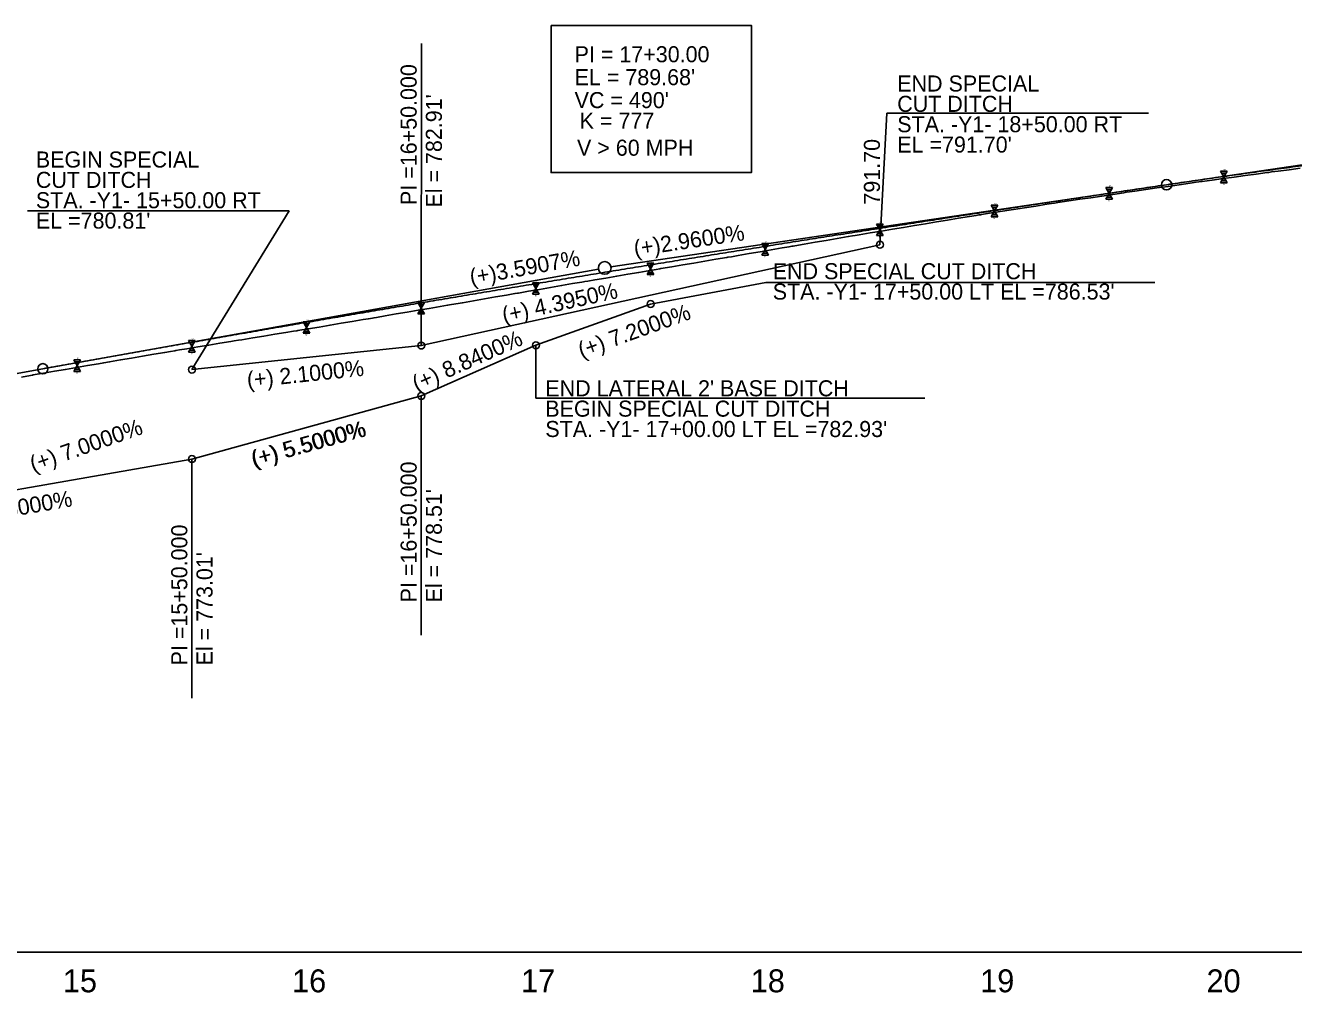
# Model space of a CAD drawing. Extents: x 579185 to 595036, y -53221 to -44640.
# Drawn here: x 579799 to 580352, y -48575 to -48153 of the extents above; entities that cross this region are included whole.
import ezdxf

# ---------------------------------------------------------------- set-up
doc = ezdxf.new("R2010")
doc.units = 0
for name, color, linetype in [('Exist Profile Cell', 7, 'Continuous'), ('Exist Vertical Profile Ground Line', 7, 'Continuous'), ('Exist Vertical Profile Horizontal Axis Label Major', 7, 'Continuous'), ('Old_Level_2', 7, 'Continuous'), ('Prop Grid Mask', 7, 'Continuous'), ('Prop Vertical Profile Curve Label', 7, 'Continuous'), ('Prop Vertical Profile Ditch Grade Left', 7, 'Continuous'), ('Prop Vertical Profile Ditch Grade Left Label', 7, 'Continuous'), ('Prop Vertical Profile Ditch Grade Right', 7, 'Continuous'), ('Prop Vertical Profile Ditch Grade Right Label', 7, 'Continuous'), ('Prop Vertical Profile Grade', 7, 'Continuous'), ('Prop Vertical Profile Grade Label', 7, 'Continuous'), ('Prop VPI Ditch Grade Left Label', 7, 'Continuous'), ('Prop VPI Ditch Grade Right Label', 7, 'Continuous'), ('Prop VPI Label', 7, 'Continuous')]:
    doc.layers.add(name, color=color, linetype=linetype)

msp = doc.modelspace()

# ---------------------------------------------------------------- linework, layer by layer
at = {"layer": 'Exist Profile Cell'}
msp.add_line((579321.48, -48557.09), (581829.78, -48557.09), dxfattribs=at)
at = {"layer": 'Exist Vertical Profile Ground Line'}
for points in [[(580280.35, -48225.53), (580282.65, -48225.19), (580287.46, -48224.5), (580292.27, -48223.81), (580297.08, -48223.12), (580301.88, -48222.43), (580306.69, -48221.74), (580309.31, -48221.37), (580310.58, -48221.18), (580311.5, -48221.05), (580311.91, -48220.99), (580316.31, -48220.39), (580321.11, -48219.73), (580325.92, -48219.07), (580330.73, -48218.42), (580335.53, -48217.76), (580340.34, -48217.11), (580341, -48217.02), (580342.22, -48216.86), (580345.15, -48216.48), (580349.96, -48215.86), (580354.76, -48215.24)], [(579922.11, -48285.28), (579926.92, -48284.47), (579931.72, -48283.65), (579936.53, -48282.84), (579941.34, -48282.04), (579946.15, -48281.23), (579948.41, -48280.85), (579950.18, -48280.56), (579950.95, -48280.42), (579951.95, -48280.26), (579955.76, -48279.6), (579960.57, -48278.78), (579965.37, -48277.97), (579970.18, -48277.15), (579974.99, -48276.33), (579979.8, -48275.52), (579982.96, -48274.99), (579984.67, -48274.68), (579989.41, -48273.86), (579994.22, -48273.03), (579999.03, -48272.2), (580003.83, -48271.37), (580008.64, -48270.55), (580012.3, -48269.92), (580013.45, -48269.72), (580013.83, -48269.65), (580018.25, -48268.88), (580023.06, -48268.05), (580027.87, -48267.22), (580032.68, -48266.39), (580037.48, -48265.56), (580041.5, -48264.87), (580042.29, -48264.74), (580042.84, -48264.65), (580044.15, -48264.44), (580047.1, -48263.93), (580051.91, -48263.11), (580056.71, -48262.29), (580061.52, -48261.47), (580066.33, -48260.65), (580071.13, -48259.84), (580073.84, -48259.38), (580075.45, -48259.1), (580075.94, -48259.02), (580080.75, -48258.2), (580085.56, -48257.38), (580090.36, -48256.57), (580095.17, -48255.75), (580099.98, -48254.94), (580104.79, -48254.13), (580105.11, -48254.07), (580106.69, -48253.8), (580109.59, -48253.3), (580114.4, -48252.47), (580119.21, -48251.65), (580124.01, -48250.82), (580128.82, -48250), (580131.84, -48249.48), (580133.1, -48249.27), (580133.63, -48249.17), (580134.36, -48249.05), (580138.44, -48248.34), (580143.24, -48247.51), (580148.05, -48246.69), (580152.86, -48245.86), (580157.67, -48245.04), (580159.56, -48244.71), (580160.62, -48244.54), (580162.47, -48244.22), (580167.28, -48243.41), (580172.09, -48242.61), (580176.89, -48241.8), (580181.7, -48241), (580186.58, -48240.18), (580187.61, -48240.01), (580191.32, -48239.41), (580196.12, -48238.62), (580200.93, -48237.83), (580205.74, -48237.05), (580210.55, -48236.27), (580213.45, -48235.8), (580214.63, -48235.6), (580215.35, -48235.49), (580215.8, -48235.42), (580220.16, -48234.73), (580224.97, -48233.97), (580229.77, -48233.22), (580234.58, -48232.46), (580239.39, -48231.71), (580244.2, -48230.96), (580246.21, -48230.64), (580247.52, -48230.45), (580249, -48230.22), (580253.81, -48229.5), (580258.62, -48228.78), (580263.43, -48228.06), (580268.23, -48227.34), (580273.04, -48226.62), (580277.85, -48225.9), (580279.02, -48225.72), (580280.35, -48225.53)], [(579797.19, -48306.27), (579799.51, -48305.86), (579801.93, -48305.43), (579802.34, -48305.36), (579806.73, -48304.6), (579811.54, -48303.78), (579816.35, -48302.95), (579821.16, -48302.13), (579825.96, -48301.31), (579830.77, -48300.49), (579833.05, -48300.08), (579835.58, -48299.65), (579840.39, -48298.83), (579845.19, -48298.01), (579850, -48297.19), (579854.81, -48296.37), (579859.61, -48295.55), (579862.14, -48295.13), (579864.07, -48294.79), (579864.42, -48294.74), (579866.02, -48294.47), (579869.23, -48293.94), (579874.04, -48293.15), (579878.84, -48292.36), (579883.65, -48291.58), (579888.46, -48290.79), (579889.94, -48290.55), (579891.76, -48290.25), (579893.27, -48290.01), (579898.07, -48289.22), (579902.88, -48288.44), (579907.69, -48287.65), (579912.49, -48286.87), (579915.79, -48286.33), (579917.3, -48286.09), (579917.66, -48286.03), (579922.11, -48285.28)]]:
    msp.add_lwpolyline(points, dxfattribs=at)
at = {"layer": 'Old_Level_2'}
for p, q in [((580321.48, -48219.03), (580320.04, -48216.53)), ((580320.04, -48216.53), (580322.93, -48216.53)), ((580320.04, -48221.53), (580321.48, -48219.03)), ((580320.52, -48217.36), (580322.45, -48217.36)), ((580321, -48218.2), (580321.97, -48218.2)), ((580321, -48219.87), (580321.96, -48219.87)), ((580321.48, -48219.03), (580322.93, -48216.53)), ((580322.93, -48221.53), (580321.48, -48219.03)), ((580271.48, -48226.18), (580270.04, -48223.68)), ((580270.04, -48223.68), (580272.93, -48223.68)), ((580270.52, -48224.51), (580272.45, -48224.51)), ((580271, -48225.35), (580271.97, -48225.35)), ((580271.48, -48226.18), (580272.93, -48223.68)), ((580320.04, -48221.53), (580322.93, -48221.53)), ((580320.52, -48220.7), (580322.45, -48220.7)), ((580221.48, -48233.86), (580220.04, -48231.36)), ((580220.04, -48231.36), (580222.93, -48231.37)), ((580221.48, -48233.87), (580222.93, -48231.37)), ((580270.04, -48228.68), (580271.48, -48226.18)), ((580270.04, -48228.68), (580272.93, -48228.68)), ((580270.52, -48227.85), (580272.45, -48227.85)), ((580271, -48227.02), (580271.96, -48227.02)), ((580272.93, -48228.68), (580271.48, -48226.18)), ((580220.04, -48236.37), (580221.48, -48233.87)), ((580220.04, -48236.37), (580222.93, -48236.37)), ((580220.52, -48232.2), (580222.45, -48232.2)), ((580220.52, -48235.53), (580222.45, -48235.53)), ((580221, -48233.03), (580221.96, -48233.03)), ((580221, -48234.7), (580221.96, -48234.7)), ((580222.93, -48236.37), (580221.48, -48233.86)), ((580171.48, -48242.06), (580170.04, -48239.56)), ((580170.04, -48239.56), (580172.93, -48239.56)), ((580170.04, -48244.56), (580171.48, -48242.06)), ((580170.52, -48240.39), (580172.45, -48240.39)), ((580171, -48241.23), (580171.96, -48241.23)), ((580171.48, -48242.06), (580172.93, -48239.56)), ((580172.93, -48244.56), (580171.48, -48242.06)), ((580121.48, -48250.59), (580120.04, -48248.09)), ((580120.04, -48248.09), (580122.93, -48248.1)), ((580121.48, -48250.6), (580122.93, -48248.1)), ((580170.04, -48244.56), (580172.93, -48244.56)), ((580170.52, -48243.73), (580172.45, -48243.73)), ((580171, -48242.89), (580171.96, -48242.89)), ((580120.04, -48253.1), (580121.48, -48250.6)), ((580120.04, -48253.1), (580122.93, -48253.1)), ((580120.52, -48248.93), (580122.45, -48248.93)), ((580120.52, -48252.26), (580122.45, -48252.26)), ((580121, -48249.76), (580121.96, -48249.76)), ((580121, -48251.43), (580121.96, -48251.43)), ((580122.93, -48253.1), (580121.48, -48250.59)), ((580071.48, -48259.11), (580070.04, -48256.61)), ((580070.04, -48256.61), (580072.93, -48256.61)), ((580070.04, -48261.61), (580071.48, -48259.11)), ((580070.52, -48257.44), (580072.45, -48257.44)), ((580071, -48258.28), (580071.96, -48258.28)), ((580071.48, -48259.11), (580072.93, -48256.61)), ((580072.93, -48261.61), (580071.48, -48259.11)), ((580070.04, -48261.61), (580072.93, -48261.61)), ((580070.52, -48260.78), (580072.45, -48260.78)), ((580071, -48259.94), (580071.96, -48259.94)), ((580021.48, -48267.67), (580020.04, -48265.17)), ((580020.04, -48265.17), (580022.93, -48265.18)), ((580020.04, -48270.18), (580021.48, -48267.68)), ((580020.04, -48270.18), (580022.93, -48270.18)), ((580020.52, -48266.01), (580022.45, -48266.01)), ((580020.52, -48269.34), (580022.45, -48269.34)), ((580021, -48266.84), (580021.96, -48266.84)), ((580021, -48268.51), (580021.96, -48268.51)), ((580021.48, -48267.68), (580022.93, -48265.18)), ((580022.93, -48270.18), (580021.48, -48267.67)), ((579971.48, -48276.25), (579970.04, -48273.75)), ((579970.04, -48273.75), (579972.93, -48273.75)), ((579970.52, -48274.58), (579972.45, -48274.58)), ((579971, -48275.42), (579971.96, -48275.42)), ((579971.48, -48276.25), (579972.93, -48273.75)), ((579970.04, -48278.75), (579971.48, -48276.25)), ((579970.04, -48278.75), (579972.93, -48278.75)), ((579970.52, -48277.92), (579972.45, -48277.92)), ((579971, -48277.08), (579971.96, -48277.08)), ((579972.93, -48278.75), (579971.48, -48276.25)), ((579921.48, -48284.7), (579920.04, -48282.2)), ((579920.04, -48282.2), (579922.93, -48282.2)), ((579920.04, -48287.2), (579921.48, -48284.7)), ((579920.52, -48283.03), (579922.45, -48283.03)), ((579920.52, -48286.37), (579922.45, -48286.37)), ((579921, -48283.87), (579921.96, -48283.87)), ((579921, -48285.53), (579921.96, -48285.53)), ((579921.48, -48284.7), (579922.93, -48282.2)), ((579922.93, -48287.2), (579921.48, -48284.7)), ((579871.48, -48292.89), (579870.04, -48290.39)), ((579870.04, -48290.39), (579872.93, -48290.4)), ((579870.52, -48291.23), (579872.45, -48291.23)), ((579871, -48292.06), (579871.96, -48292.06)), ((579871.48, -48292.9), (579872.93, -48290.4)), ((579920.04, -48287.2), (579922.93, -48287.2)), ((579870.04, -48295.4), (579871.48, -48292.9)), ((579870.04, -48295.4), (579872.93, -48295.4)), ((579870.52, -48294.56), (579872.45, -48294.56)), ((579871, -48293.73), (579871.96, -48293.73)), ((579872.93, -48295.4), (579871.48, -48292.89)), ((579821.48, -48301.3), (579820.04, -48298.8)), ((579820.04, -48298.8), (579822.93, -48298.8)), ((579820.04, -48303.8), (579821.48, -48301.3)), ((579820.52, -48299.63), (579822.45, -48299.63)), ((579820.52, -48302.97), (579822.45, -48302.97)), ((579821, -48300.47), (579821.96, -48300.47)), ((579821, -48302.13), (579821.96, -48302.13)), ((579821.48, -48301.3), (579822.93, -48298.8)), ((579822.93, -48303.8), (579821.48, -48301.3)), ((579820.04, -48303.8), (579822.93, -48303.8))]:
    msp.add_line(p, q, dxfattribs=at)
at = {"layer": 'Prop Grid Mask'}
msp.add_lwpolyline([(580028.09, -48152.92), (580115.45, -48152.92), (580115.45, -48217.1), (580028.09, -48217.1)], close=True, dxfattribs=at)
at = {"layer": 'Prop Vertical Profile Curve Label'}
for centre in [(580296.48, -48222.42), (580296.48, -48222.42), (580296.48, -48222.42), (579806.48, -48302.67)]:
    msp.add_circle(centre, 2.25, dxfattribs=at)
at = {"layer": 'Prop Vertical Profile Ditch Grade Left'}
msp.add_line((580021.48, -48292.44), (580071.48, -48274.44), dxfattribs=at)
msp.add_lwpolyline([(579681.48, -48371.09), (579721.48, -48368.29), (579871.48, -48342.04), (579971.48, -48314.54), (580021.48, -48292.44)], dxfattribs=at)
at = {"layer": 'Prop Vertical Profile Ditch Grade Left Label'}
for p, q in [((580071.48, -48274.44), (580121.72, -48265.03)), ((580121.72, -48265.03), (580291.34, -48265.03)), ((580021.48, -48315.48), (580021.48, -48292.44)), ((579971.48, -48418.83), (579971.48, -48314.54)), ((580021.48, -48315.48), (580191.1, -48315.48)), ((579871.48, -48446.33), (579871.48, -48342.04))]:
    msp.add_line(p, q, dxfattribs=at)
for centre in [(580071.48, -48274.44), (580021.48, -48292.44), (579971.48, -48314.54), (579871.48, -48342.04)]:
    msp.add_circle(centre, 1.5, dxfattribs=at)
at = {"layer": 'Prop Vertical Profile Ditch Grade Right'}
msp.add_lwpolyline([(579871.48, -48303.04), (579971.48, -48292.54), (580171.48, -48248.59)], dxfattribs=at)
at = {"layer": 'Prop Vertical Profile Ditch Grade Right Label'}
for p, q in [((579971.6, -48160.85), (579971.48, -48292.54)), ((580171.48, -48248.59), (580174.51, -48191.21)), ((580174.51, -48191.21), (580288.59, -48191.21)), ((579799.75, -48233.86), (579913.83, -48233.86)), ((579871.48, -48303.04), (579913.83, -48233.86))]:
    msp.add_line(p, q, dxfattribs=at)
at = {"layer": 'Prop Vertical Profile Grade'}
msp.add_line((579641.48, -48332.29), (579806.48, -48302.67), dxfattribs=at)
for points in [[(580296.48, -48222.42), (580301.48, -48221.68), (580306.48, -48220.95), (580311.48, -48220.23), (580316.48, -48219.51), (580321.48, -48218.8), (580326.48, -48218.1), (580331.48, -48217.4), (580336.48, -48216.71), (580341.48, -48216.03), (580346.48, -48215.35), (580351.48, -48214.68), (580356.48, -48214.01), (580361.48, -48213.36), (580366.48, -48212.7), (580371.48, -48212.06), (580376.48, -48211.42), (580381.48, -48210.79), (580386.48, -48210.17), (580391.48, -48209.55), (580396.48, -48208.94), (580401.48, -48208.33), (580406.48, -48207.73), (580411.48, -48207.14), (580416.48, -48206.55), (580421.48, -48205.97), (580426.48, -48205.4), (580431.48, -48204.84), (580436.48, -48204.28), (580441.48, -48203.72), (580446.48, -48203.18), (580451.48, -48202.64), (580456.48, -48202.11), (580461.48, -48201.58), (580466.48, -48201.06), (580471.48, -48200.55), (580476.48, -48200.04), (580481.48, -48199.54), (580486.48, -48199.05), (580491.48, -48198.56), (580496.48, -48198.08), (580501.48, -48197.61), (580506.48, -48197.14), (580511.48, -48196.68), (580516.48, -48196.22), (580521.48, -48195.78), (580526.48, -48195.34), (580531.48, -48194.9), (580536.48, -48194.47), (580541.48, -48194.05), (580546.48, -48193.64)], [(579806.48, -48302.67), (579816.28, -48300.91), (579826.08, -48299.16), (579835.88, -48297.42), (579845.68, -48295.68), (579855.48, -48293.95), (579865.28, -48292.22), (579875.08, -48290.5), (579884.88, -48288.79), (579894.68, -48287.08), (579904.48, -48285.38), (579914.28, -48283.69), (579924.08, -48282), (579933.88, -48280.32), (579943.68, -48278.64), (579953.48, -48276.97), (579963.28, -48275.31), (579973.08, -48273.65), (579982.88, -48272), (579992.68, -48270.35), (580002.48, -48268.71), (580012.28, -48267.08), (580022.08, -48265.45), (580031.88, -48263.83), (580041.68, -48262.22), (580051.48, -48260.61), (580061.28, -48259.01), (580071.08, -48257.41), (580080.88, -48255.83), (580090.68, -48254.24), (580100.48, -48252.66), (580110.28, -48251.09), (580120.08, -48249.53), (580129.88, -48247.97), (580139.68, -48246.42), (580149.48, -48244.87), (580159.28, -48243.33), (580169.08, -48241.8), (580178.88, -48240.27), (580188.68, -48238.75), (580198.48, -48237.23), (580208.28, -48235.72), (580218.08, -48234.22), (580227.88, -48232.72), (580237.68, -48231.23), (580247.48, -48229.75), (580257.28, -48228.27), (580267.08, -48226.8), (580276.88, -48225.33), (580286.68, -48223.87), (580296.48, -48222.42)]]:
    msp.add_spline(points, degree=3, dxfattribs=at)
at = {"layer": 'Prop VPI Ditch Grade Right Label'}
for centre in [(580171.48, -48248.59), (579971.48, -48292.54), (579871.48, -48303.04)]:
    msp.add_circle(centre, 1.5, dxfattribs=at)
at = {"layer": 'Prop VPI Label'}
for p, q in [((580296.48, -48222.42), (580418.76, -48204.32)), ((580296.48, -48222.42), (580054.2, -48258.28)), ((579806.48, -48302.67), (580048.78, -48259.17))]:
    msp.add_line(p, q, dxfattribs=at)
msp.add_circle((580051.48, -48258.68), 2.75, dxfattribs=at)

# ---------------------------------------------------------------- texts
at = {"layer": 'Exist Vertical Profile Horizontal Axis Label Major'}
for s, p in [('15', (579815.22, -48574.59)), ('16', (579915.16, -48574.59)), ('17', (580015.02, -48574.59)), ('18', (580115.15, -48574.59)), ('19', (580215.19, -48574.59)), ('20', (580313.87, -48574.59))]:
    msp.add_text(s, height=10, dxfattribs=at).set_placement(p)
at = {"layer": 'Old_Level_2'}
for p in [(580321.25, -48216.37), (580271.25, -48223.52), (580321.06, -48222.54), (580221.25, -48231.21), (580271.06, -48229.69), (580221.06, -48237.37), (580171.25, -48239.4), (580121.25, -48247.94), (580171.06, -48245.56), (580121.06, -48254.1), (580071.25, -48256.45), (580021.25, -48265.02), (580071.06, -48262.61), (580021.06, -48271.18), (579971.25, -48273.59), (579921.25, -48282.04), (579971.06, -48279.75), (579871.25, -48290.24), (579921.06, -48288.2), (579821.25, -48298.64), (579871.06, -48296.4), (579821.06, -48304.8)]:
    msp.add_text('6"', height=0.8, dxfattribs=at).set_placement(p)
at = {"layer": 'Prop Vertical Profile Curve Label'}
for s, p in [("VC = 490'", (580038.35, -48189.01)), ('K = 777', (580040.56, -48197.98)), ('V > 60 MPH', (580039.4, -48209.77))]:
    msp.add_text(s, height=7, dxfattribs=at).set_placement(p)
at = {"layer": 'Prop Vertical Profile Ditch Grade Left Label'}
for s, p in [('END SPECIAL CUT DITCH', (580124.74, -48263.63)), ("STA. -Y1- 17+50.00 LT EL =786.53'", (580124.74, -48272.51)), ("END LATERAL 2' BASE DITCH", (580025.58, -48314.69)), ('BEGIN SPECIAL CUT DITCH', (580025.58, -48323.56)), ("STA. -Y1- 17+00.00 LT EL =782.93'", (580025.58, -48332.44))]:
    msp.add_text(s, height=7, dxfattribs=at).set_placement(p)
for s, rotation, p in [('(+) 7.2000%', 19.7989, (580041.39, -48298.15)), ('(+) 8.8400%', 23.8454, (579969.48, -48312.72)), ('(+) 5.5000%', 15.3763, (579898.36, -48345.54)), ('(+) 5.5000%', 15.3763, (579898.63, -48345.46)), ('(+) 3.5000%', 9.9262, (579769.25, -48371.39))]:
    msp.add_text(s, height=7, rotation=rotation, dxfattribs=at).set_placement(p)
at = {"layer": 'Prop Vertical Profile Ditch Grade Right'}
for s, p in [('END SPECIAL ', (580179.02, -48181.77)), ('CUT DITCH', (580179.02, -48190.65)), ('STA. -Y1- 18+50.00 RT ', (580179.02, -48199.52)), ("EL =791.70'", (580179.02, -48208.4)), ('BEGIN SPECIAL ', (579803.44, -48214.92)), ('CUT DITCH', (579803.44, -48223.8)), ('STA. -Y1- 15+50.00 RT ', (579803.44, -48232.67)), ("EL =780.81'", (579803.44, -48241.55))]:
    msp.add_text(s, height=7, dxfattribs=at).set_placement(p)
at = {"layer": 'Prop Vertical Profile Ditch Grade Right Label'}
for s, rotation, p in [('(+) 4.3950%', 12.3938, (580007.58, -48282.78)), ('(+) 2.1000%', 5.9941, (579895.82, -48311.04)), ('(+) 7.0000%', 19.29, (579802.28, -48347.85))]:
    msp.add_text(s, height=7, rotation=rotation, dxfattribs=at).set_placement(p)
at = {"layer": 'Prop Vertical Profile Grade Label'}
for s, rotation, p in [('(+)2.9600%', 8.4187, (580064.68, -48253.7)), ('(+)3.5907%', 10.1783, (579993.27, -48266.22))]:
    msp.add_text(s, height=7, rotation=rotation, dxfattribs=at).set_placement(p)
at = {"layer": 'Prop VPI Ditch Grade Left Label'}
for s, p in [('PI =16+50.000', (579969.48, -48404.54)), ('PI =16+50.000', (579969.48, -48404.54)), ("El = 778.51'", (579980.48, -48404.54)), ('El = 778.51', (579980.48, -48404.54)), ('PI =15+50.000', (579869.48, -48432.04)), ('PI =15+50.000', (579869.48, -48432.04)), ("El = 773.01'", (579880.48, -48432.04)), ('El = 773.01', (579880.48, -48432.04))]:
    msp.add_text(s, height=7, rotation=90, dxfattribs=at).set_placement(p)
at = {"layer": 'Prop VPI Ditch Grade Right Label'}
for s, p in [('PI =16+50.000', (579969.48, -48231.26)), ("El = 782.91'", (579980.48, -48232.38)), ('791.70', (580171.48, -48231.09))]:
    msp.add_text(s, height=7, rotation=90, dxfattribs=at).set_placement(p)
at = {"layer": 'Prop VPI Label'}
for s, p in [('PI = 17+30.00', (580038.35, -48169.01)), ("EL = 789.68'", (580038.35, -48179.01))]:
    msp.add_text(s, height=7, dxfattribs=at).set_placement(p)

doc.saveas('drawing.dxf')
